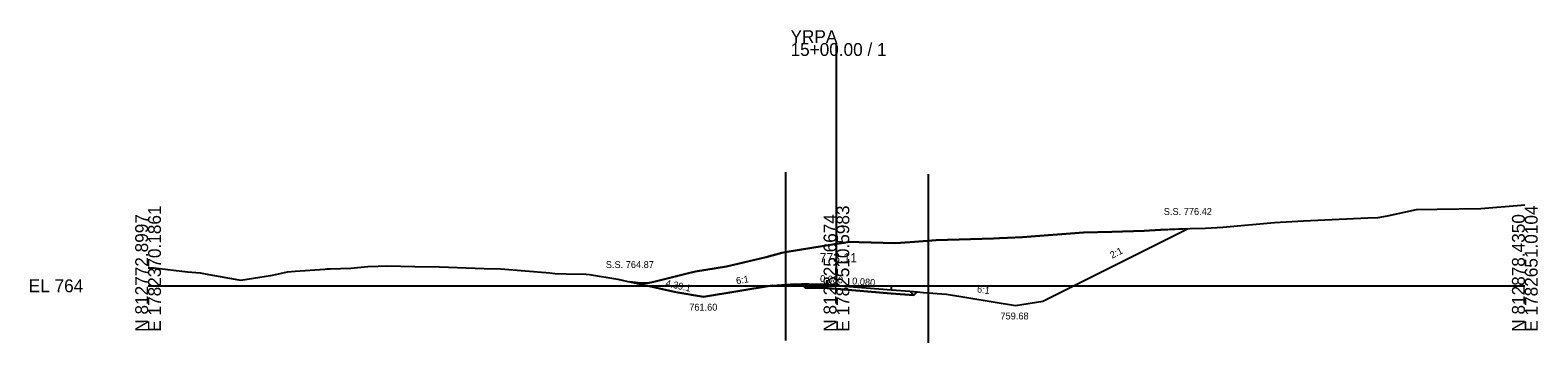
# Model space of a CAD drawing. Extents: x -26 to 2603, y -14 to 9545.
# Drawn here: x -25.7 to 302.8, y 4987.6 to 5055.6 of the extents above; entities that cross this region are included whole.
import ezdxf

# ---------------------------------------------------------------- set-up
doc = ezdxf.new("R2010")
doc.units = 0
for name, color, linetype in [('Exist Cross Section Cell', 7, 'Continuous'), ('Exist XS Center Line Elevation Label', 7, 'Continuous'), ('Exist XS Ground Line', 7, 'Continuous'), ('Prop XS Ditch Slope Text', 7, 'Continuous'), ('Prop XS Ditch Standard Text', 7, 'Continuous'), ('Prop XS Dump Level', 7, 'Continuous'), ('Prop XS Earthwork Shape', 7, 'Continuous'), ('Prop XS EOT Tick Mark', 7, 'Continuous'), ('Prop XS Exc Vertical Line 1', 7, 'Continuous'), ('Prop XS Exc Vertical Line 2', 7, 'Continuous'), ('Prop XS Finish Grade', 7, 'Continuous'), ('Prop XS Finish Grade Earthwork', 7, 'Continuous'), ('Prop XS Finish Grade Paved Shoulder', 7, 'Continuous'), ('Prop XS Finish Grade Pavement', 7, 'Continuous'), ('Prop XS Hydro Typical Ditch Data', 7, 'Continuous'), ('Prop XS Pvmt Edge Slope', 7, 'Continuous'), ('Prop XS SE Text', 7, 'Continuous'), ('Prop XS Side Slope Text', 7, 'Continuous'), ('Prop XS SS Elevation Text', 7, 'Continuous'), ('Prop XS Subgrade Earthwork', 7, 'Continuous'), ('Scratch_Level_6', 7, 'Continuous')]:
    doc.layers.add(name, color=color, linetype=linetype)

msp = doc.modelspace()

# ---------------------------------------------------------------- linework, layer by layer
at = {"layer": 'Exist Cross Section Cell'}
for p, q in [((150, 5000), (150, 5052.84)), ((0, 5000), (150, 5000)), ((150, 5000), (300, 5000))]:
    msp.add_line(p, q, dxfattribs=at)
at = {"layer": 'Exist XS Ground Line'}
for p, q in [((280.89, 5016.66), (290.41, 5016.86)), ((290.41, 5016.86), (299.23, 5017.53)), ((299.23, 5017.53), (300, 5017.61)), ((234.21, 5012.76), (245.44, 5013.75)), ((245.44, 5013.75), (251.78, 5014.11)), ((251.78, 5014.11), (265.8, 5014.79)), ((265.8, 5014.79), (268.02, 5014.9)), ((268.02, 5014.9), (270.09, 5015.25)), ((270.09, 5015.25), (276.39, 5016.58)), ((276.39, 5016.58), (280.89, 5016.66)), ((171.72, 5009.95), (184.26, 5010.31)), ((184.26, 5010.31), (185.52, 5010.36)), ((185.52, 5010.36), (187.24, 5010.44)), ((187.24, 5010.44), (190.54, 5010.6)), ((190.54, 5010.6), (203.81, 5011.64)), ((203.81, 5011.64), (210.04, 5011.77)), ((210.04, 5011.77), (217.08, 5011.97)), ((217.08, 5011.97), (220.6, 5012.17)), ((220.6, 5012.17), (227.1, 5012.44)), ((227.1, 5012.44), (230.4, 5012.55)), ((230.4, 5012.55), (234.21, 5012.76)), ((134.72, 5006.27), (138.13, 5007.21)), ((138.13, 5007.21), (138.86, 5007.35)), ((138.86, 5007.35), (150, 5009.11)), ((150, 5009.11), (151.72, 5009.38)), ((151.72, 5009.38), (152.8, 5009.57)), ((152.8, 5009.57), (154.91, 5009.49)), ((154.91, 5009.49), (162.9, 5009.31)), ((162.9, 5009.31), (166.05, 5009.49)), ((166.05, 5009.49), (171.72, 5009.95)), ((0, 5003.93), (1.25, 5003.94)), ((1.25, 5003.94), (8.57, 5003.02)), ((32.09, 5003.22), (38.52, 5003.65)), ((38.52, 5003.65), (38.92, 5003.67)), ((38.92, 5003.67), (39.7, 5003.72)), ((39.7, 5003.72), (44.21, 5003.85)), ((44.21, 5003.85), (47.9, 5004.23)), ((47.9, 5004.23), (50.11, 5004.3)), ((50.11, 5004.3), (51.95, 5004.37)), ((51.95, 5004.37), (58.13, 5004.23)), ((58.13, 5004.23), (63.53, 5004.1)), ((63.53, 5004.1), (73.22, 5003.78)), ((73.22, 5003.78), (76.82, 5003.66)), ((76.82, 5003.66), (77.74, 5003.59)), ((77.74, 5003.59), (81.29, 5003.35)), ((119.31, 5003.1), (126.08, 5004.17)), ((126.08, 5004.17), (134.72, 5006.27)), ((8.57, 5003.02), (11.37, 5002.86)), ((11.37, 5002.86), (12.44, 5002.64)), ((12.44, 5002.64), (19.75, 5001.3)), ((19.75, 5001.3), (20.21, 5001.25)), ((20.21, 5001.25), (21.58, 5001.42)), ((21.58, 5001.42), (27.11, 5002.34)), ((27.11, 5002.34), (30.38, 5003.03)), ((30.38, 5003.03), (32.09, 5003.22)), ((81.29, 5003.35), (87.53, 5002.79)), ((87.53, 5002.79), (88.64, 5002.71)), ((88.64, 5002.71), (91.11, 5002.64)), ((91.11, 5002.64), (95.47, 5002.54)), ((95.47, 5002.54), (96.2, 5002.43)), ((96.2, 5002.43), (102.34, 5001.47)), ((102.34, 5001.47), (104.54, 5000.93)), ((104.54, 5000.93), (106.77, 5000.68)), ((106.77, 5000.68), (108.81, 5000.54)), ((108.81, 5000.54), (110.22, 5000.88)), ((110.22, 5000.88), (117.73, 5002.74)), ((117.73, 5002.74), (119.31, 5003.1))]:
    msp.add_line(p, q, dxfattribs=at)
at = {"layer": 'Prop XS Dump Level'}
for p, q in [((148, 5000.26), (150, 5000.1)), ((150, 5000.1), (162, 4999.14))]:
    msp.add_line(p, q, dxfattribs=at)
at = {"layer": 'Prop XS Earthwork Shape'}
msp.add_lwpolyline([(166.86, 4997.96), (167.6, 4998.69), (169, 4998.58), (174, 4998.18), (189, 4995.68), (195, 4996.68), (226.48, 5012.42), (220.6, 5012.17), (217.08, 5011.97), (210.04, 5011.77), (203.81, 5011.64), (190.54, 5010.6), (187.24, 5010.44), (185.52, 5010.36), (184.26, 5010.31), (171.72, 5009.95), (166.05, 5009.49), (162.9, 5009.31), (154.91, 5009.49), (152.8, 5009.57), (151.72, 5009.38), (150, 5009.11), (138.86, 5007.35), (138.13, 5007.21), (134.72, 5006.27), (126.08, 5004.17), (119.31, 5003.1), (117.73, 5002.74), (110.22, 5000.88), (108.81, 5000.54), (106.77, 5000.68), (105, 5000.87), (115, 4998.6), (121, 4997.6), (136, 5000.1), (141, 5000.4), (142.42, 5000.37), (143.22, 4999.56), (147.96, 4999.47), (149.94, 4999.31), (161.94, 4998.35)], close=True, dxfattribs=at)
at = {"layer": 'Prop XS EOT Tick Mark'}
for p, q in [((148, 5000.26), (148, 5001.26)), ((162, 4999.14), (162, 5000.14))]:
    msp.add_line(p, q, dxfattribs=at)
at = {"layer": 'Prop XS Exc Vertical Line 1'}
msp.add_line((139, 4988.07), (139, 5024.76), dxfattribs=at)
at = {"layer": 'Prop XS Exc Vertical Line 2'}
msp.add_line((170.06, 4987.59), (170.06, 5024.28), dxfattribs=at)
at = {"layer": 'Prop XS Finish Grade'}
for p, q in [((144, 5000.34), (142.42, 5000.37)), ((166, 4998.82), (167.6, 4998.69))]:
    msp.add_line(p, q, dxfattribs=at)
at = {"layer": 'Prop XS Finish Grade Earthwork'}
for p, q in [((195, 4996.68), (226.48, 5012.42)), ((115, 4998.6), (105, 5000.87)), ((136, 5000.1), (141, 5000.4)), ((141, 5000.4), (142.42, 5000.37)), ((121, 4997.6), (115, 4998.6)), ((136, 5000.1), (121, 4997.6)), ((167.6, 4998.69), (169, 4998.58)), ((169, 4998.58), (174, 4998.18)), ((174, 4998.18), (189, 4995.68)), ((189, 4995.68), (195, 4996.68))]:
    msp.add_line(p, q, dxfattribs=at)
at = {"layer": 'Prop XS Finish Grade Paved Shoulder'}
for p, q in [((148, 5000.26), (144, 5000.34)), ((162, 4999.14), (166, 4998.82))]:
    msp.add_line(p, q, dxfattribs=at)
at = {"layer": 'Prop XS Finish Grade Pavement'}
for p, q in [((148, 5000.26), (150, 5000.1)), ((150, 5000.1), (162, 4999.14))]:
    msp.add_line(p, q, dxfattribs=at)
at = {"layer": 'Prop XS Hydro Typical Ditch Data'}
for p, q in [((115, 4998.6), (105, 5000.87)), ((121, 4997.6), (115, 4998.6))]:
    msp.add_line(p, q, dxfattribs=at)
at = {"layer": 'Prop XS Pvmt Edge Slope'}
for p, q in [((144, 5000.34), (143.22, 4999.56)), ((166, 4998.82), (166.86, 4997.96))]:
    msp.add_line(p, q, dxfattribs=at)
at = {"layer": 'Prop XS Subgrade Earthwork'}
for p, q in [((143.22, 4999.56), (142.42, 5000.37)), ((147.96, 4999.47), (143.22, 4999.56)), ((147.96, 4999.47), (149.94, 4999.31)), ((149.94, 4999.31), (161.94, 4998.35)), ((161.94, 4998.35), (166.86, 4997.96)), ((166.86, 4997.96), (167.6, 4998.69))]:
    msp.add_line(p, q, dxfattribs=at)
at = {"layer": 'Scratch_Level_6'}
msp.add_lwpolyline([(147.96, 4999.47), (143.22, 4999.56), (142.42, 5000.37), (144, 5000.34), (148, 5000.26), (150, 5000.1), (162, 4999.14), (166, 4998.82), (167.6, 4998.69), (166.86, 4997.96), (161.94, 4998.35), (149.94, 4999.31)], close=True, dxfattribs=at)

# ---------------------------------------------------------------- texts
at = {"layer": 'Exist Cross Section Cell'}
for s, p in [('YRPA', (140, 5052.84)), ('15+00.00 / 1', (140, 5050.04)), ('EL 764', (-26, 4998.6))]:
    msp.add_text(s, height=2.8, dxfattribs=at).set_placement(p)
for s, p in [('E 1782370.1861', (2.8, 4990)), ('E 1782510.5983', (152.8, 4990)), ('E 1782651.0104', (302.8, 4990)), ('N 812772.8997', (0, 4990)), ('N 812825.6674', (150, 4990)), ('N 812878.4350', (300, 4990))]:
    msp.add_text(s, height=2.8, rotation=90, dxfattribs=at).set_placement(p)
at = {"layer": 'Exist XS Center Line Elevation Label'}
msp.add_text('773.11', height=2, dxfattribs=at).set_placement((146.32, 5005.11))
at = {"layer": 'Prop XS Ditch Slope Text'}
for rotation, p in [(9.4623, (128.25, 5000.33)), (350.5377, (180.55, 4998.61))]:
    msp.add_text('6:1', height=1.5, rotation=rotation, dxfattribs=at).set_placement(p)
at = {"layer": 'Prop XS Ditch Standard Text'}
for s, p in [('761.60', (117.92, 4994.6)), ('759.68', (185.74, 4992.68))]:
    msp.add_text(s, height=1.5, dxfattribs=at).set_placement(p)
at = {"layer": 'Prop XS Dump Level'}
for p in [(136, 5000.06), (174, 4998.14)]:
    msp.add_text('Case4', height=0.04, dxfattribs=at).set_placement(p)
at = {"layer": 'Prop XS SE Text'}
for p in [(146.38, 5000.89), (153.38, 5000.33)]:
    msp.add_text('0.080', height=1.5, rotation=355.4261, dxfattribs=at).set_placement(p)
at = {"layer": 'Prop XS Side Slope Text'}
for s, rotation, p in [('2:1', 26.5651, (210.07, 5005.89)), ('4.39:1', 347.1753, (112.66, 4999.93))]:
    msp.add_text(s, height=1.5, rotation=rotation, dxfattribs=at).set_placement(p)
at = {"layer": 'Prop XS SS Elevation Text'}
for s, p in [('S.S. 776.42', (221.33, 5015.42)), ('S.S. 764.87', (99.74, 5003.87))]:
    msp.add_text(s, height=1.5, dxfattribs=at).set_placement(p)

doc.saveas('drawing.dxf')
